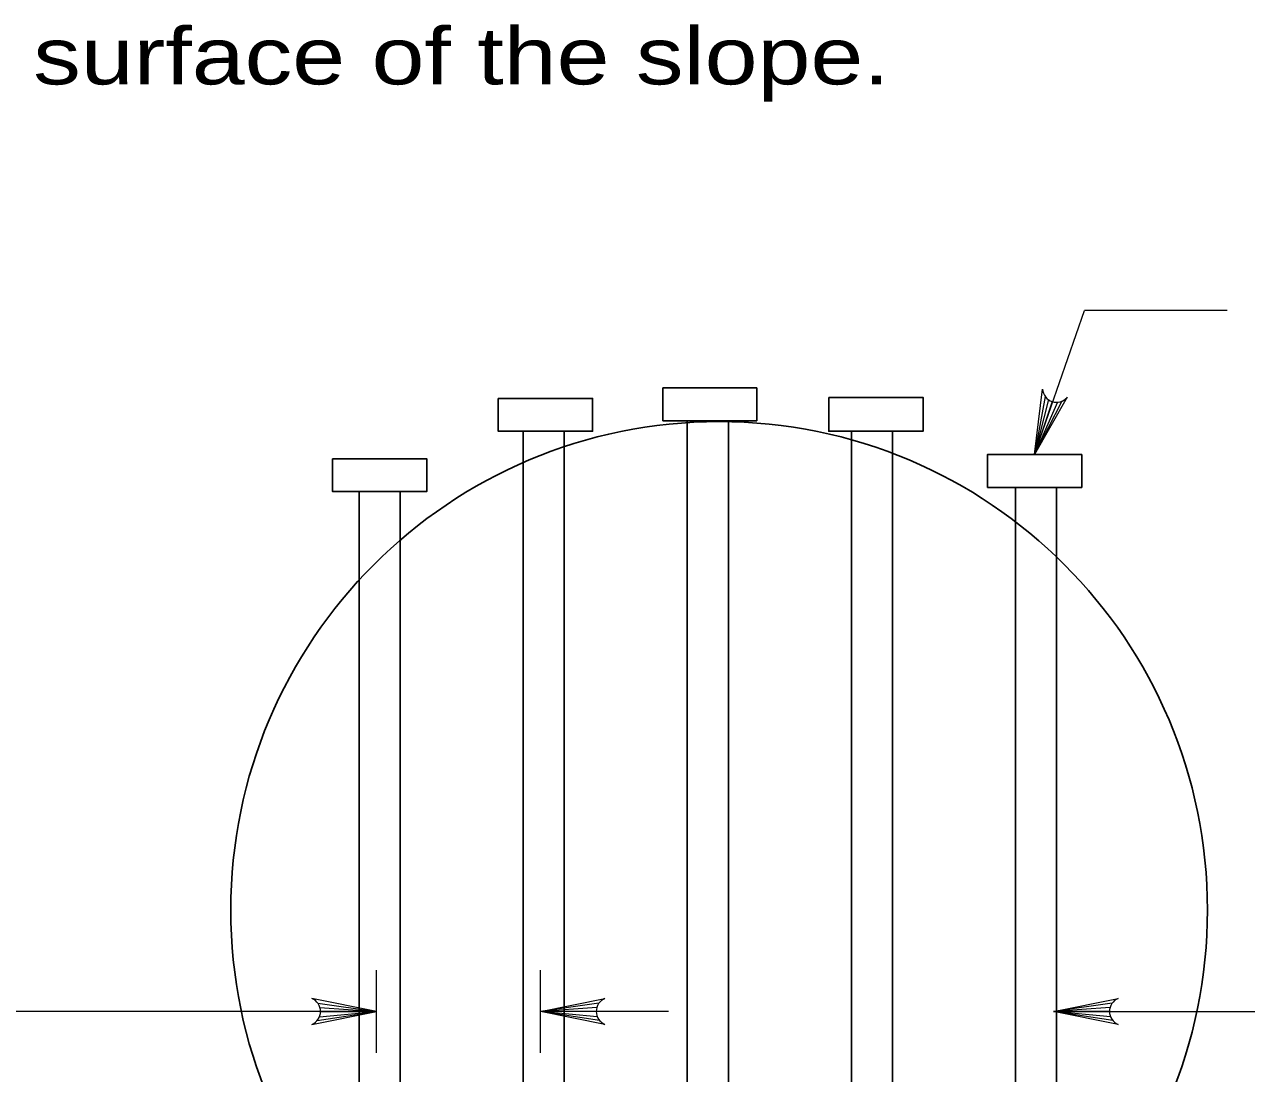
# Model space of a CAD drawing. Extents: x 1083.1 to 1117.1, y 697.4 to 741.4.
# Drawn here: x 1101.675 to 1105.026, y 731.398 to 734.273 of the extents above; entities that cross this region are included whole.
import ezdxf

# ---------------------------------------------------------------- set-up
doc = ezdxf.new("R2010")
doc.units = 0
doc.header["$LTSCALE"] = 0.062
doc.layers.add('1', color=7, linetype='Continuous', lineweight=13)

msp = doc.modelspace()

# ---------------------------------------------------------------- linework, layer by layer
at = {"layer": '1'}
for p, q in [((1104.4445, 733.09425), (1104.58125, 733.48958)), ((1104.97225, 733.48958), (1104.58125, 733.48958)), ((1104.4735, 733.2535), (1104.4445, 733.09425)), ((1104.48233, 733.24483), (1104.4445, 733.09425)), ((1104.51892, 733.24042), (1104.4445, 733.09425)), ((1104.49258, 733.23975), (1104.4445, 733.09425)), ((1104.50717, 733.23792), (1104.4445, 733.09425)), ((1102.63992, 731.45458), (1102.63992, 731.68117)), ((1103.08975, 731.45458), (1103.08975, 731.68117)), ((1102.47967, 731.59025), (1102.63992, 731.56783)), ((1103.24992, 731.59025), (1103.08975, 731.56783)), ((1104.65692, 731.59025), (1104.49667, 731.56783)), ((1102.63992, 731.56783), (1099.71408, 731.56783)), ((1102.47783, 731.54308), (1102.63992, 731.56783)), ((1102.48392, 731.5535), (1102.63992, 731.56783)), ((1102.48508, 731.57917), (1102.63992, 731.56783)), ((1102.48675, 731.56783), (1102.63992, 731.56783)), ((1103.2445, 731.57917), (1103.08975, 731.56783)), ((1103.44075, 731.56783), (1103.08975, 731.56783)), ((1103.24292, 731.56783), (1103.08975, 731.56783)), ((1103.24567, 731.5535), (1103.08975, 731.56783)), ((1103.25183, 731.54308), (1103.08975, 731.56783)), ((1104.6515, 731.57917), (1104.49667, 731.56783)), ((1104.64983, 731.56783), (1104.49667, 731.56783)), ((1104.65267, 731.5535), (1104.49667, 731.56783)), ((1104.65883, 731.54308), (1104.49667, 731.56783)), ((1104.49667, 731.56783), (1105.834, 731.56783))]:
    msp.add_line(p, q, dxfattribs=at)
at = {"layer": '1', "lineweight": 25}
for p, q in [((1103.42517, 733.27767), (1103.68342, 733.27767)), ((1103.42517, 733.27767), (1103.42517, 733.18708)), ((1103.68342, 733.27767), (1103.68342, 733.18708)), ((1103.42517, 733.18708), (1103.68342, 733.18708)), ((1103.49242, 730.37225), (1103.49242, 733.18733)), ((1103.60492, 730.37225), (1103.60492, 733.18442)), ((1103.04267, 730.42108), (1103.04267, 733.15825)), ((1103.94225, 730.42108), (1103.94225, 733.15825)), ((1104.05467, 730.42108), (1104.05467, 733.15825)), ((1104.392, 730.61167), (1104.392, 733.00433)), ((1104.5045, 730.61167), (1104.5045, 733.00433)), ((1102.70533, 730.63), (1102.70533, 732.99275))]:
    msp.add_line(p, q, dxfattribs=at)
at = {"layer": '1'}
for points in [[(1104.53367, 733.25125), (1104.4445, 733.09425), (1104.46642, 733.27342)], [(1102.46292, 731.5325), (1102.63992, 731.56783), (1102.46292, 731.60325)], [(1103.26675, 731.5325), (1103.08975, 731.56783), (1103.26675, 731.60325)], [(1104.67367, 731.5325), (1104.49667, 731.56783), (1104.67367, 731.60325)]]:
    msp.add_lwpolyline(points, dxfattribs=at)
at = {"layer": '1', "lineweight": 25}
for points in [[(1102.97425, 733.24817), (1103.23258, 733.24817), (1103.23258, 733.15825), (1102.97425, 733.15825)], [(1103.88033, 733.25083), (1104.13867, 733.25083), (1104.13867, 733.15825), (1103.88033, 733.15825)], [(1102.52, 733.08267), (1102.77825, 733.08267), (1102.77825, 732.99275), (1102.52, 732.99275)], [(1104.31533, 733.00433), (1104.31533, 733.09425), (1104.57367, 733.09425), (1104.57367, 733.00433)]]:
    msp.add_lwpolyline(points, close=True, dxfattribs=at)
for points in [[(1103.15508, 730.42108), (1103.15508, 731.26392), (1103.15508, 733.15825)], [(1102.59283, 730.63), (1102.59283, 731.25842), (1102.59283, 732.99275)]]:
    msp.add_lwpolyline(points, dxfattribs=at)
msp.add_circle((1103.57962, 731.84588), 1.33878, dxfattribs=at)
at = {"layer": '1'}
for centre, start, end in [((1104.50452, 733.27592), 183.78813, 319.61426), ((1102.44863, 731.56791), 292.08605, 67.91218), ((1103.28101, 731.56791), 112.08782, 247.91395), ((1104.68796, 731.56791), 112.08782, 247.91395)]:
    msp.add_arc(centre, 0.0382, start, end, dxfattribs=at)

# ---------------------------------------------------------------- texts
at = {"layer": '1', "width": 1.25}
msp.add_text('surface of the slope.', height=0.156, dxfattribs=at).set_placement((1101.69925, 734.109))

doc.saveas('drawing.dxf')
